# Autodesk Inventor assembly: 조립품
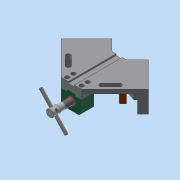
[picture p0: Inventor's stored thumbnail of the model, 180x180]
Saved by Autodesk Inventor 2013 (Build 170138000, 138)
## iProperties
Created: 2019-04
Part Number: 조립품
Document SubType Name: Assembly
Designer: dgall
Author: dgall
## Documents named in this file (11)
- C:\Users\dgall\Desktop\490407V1001\조립품.iam
- C:\Users\dgall\Desktop\490407V1001\본체.ipt
- C:\Users\dgall\Desktop\490407V1001\리드스크류.ipt
- C:\Users\dgall\Desktop\490407V1001\부시.ipt
- C:\Users\dgall\Desktop\490407V1001\서포트.ipt
- C:\Users\dgall\Desktop\490407V1001\조.ipt
- C:\Users\dgall\Desktop\490407V1001\평행 핀 2.5x24.ipt
- C:\Users\dgall\Desktop\490407V1001\핸들.ipt
- C:\Users\dgall\Desktop\490407V1001\멈춤나사 M4x5.ipt
- C:\Users\dgall\Desktop\490407V1001\멈춤나사 M4x10.ipt
- C:\Users\dgall\Desktop\490407V1001\볼트 M4x16.ipt
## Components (1 placed, 1 different names)
1. 핸들:1 — 플러쉬:1
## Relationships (1: Flush 1)
- 플러쉬:1 [Flush]: 핸들:1
